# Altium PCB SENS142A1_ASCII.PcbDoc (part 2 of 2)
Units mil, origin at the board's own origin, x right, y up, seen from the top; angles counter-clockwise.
Board outline 2760 x 2518.85 mil, 4 copper layers (Top Layer, Signal Layer 1, Signal Layer 2, Bottom Layer), stack 62.2 mil thick; 50 components, 21 nets, 98 pads, 258 vias.
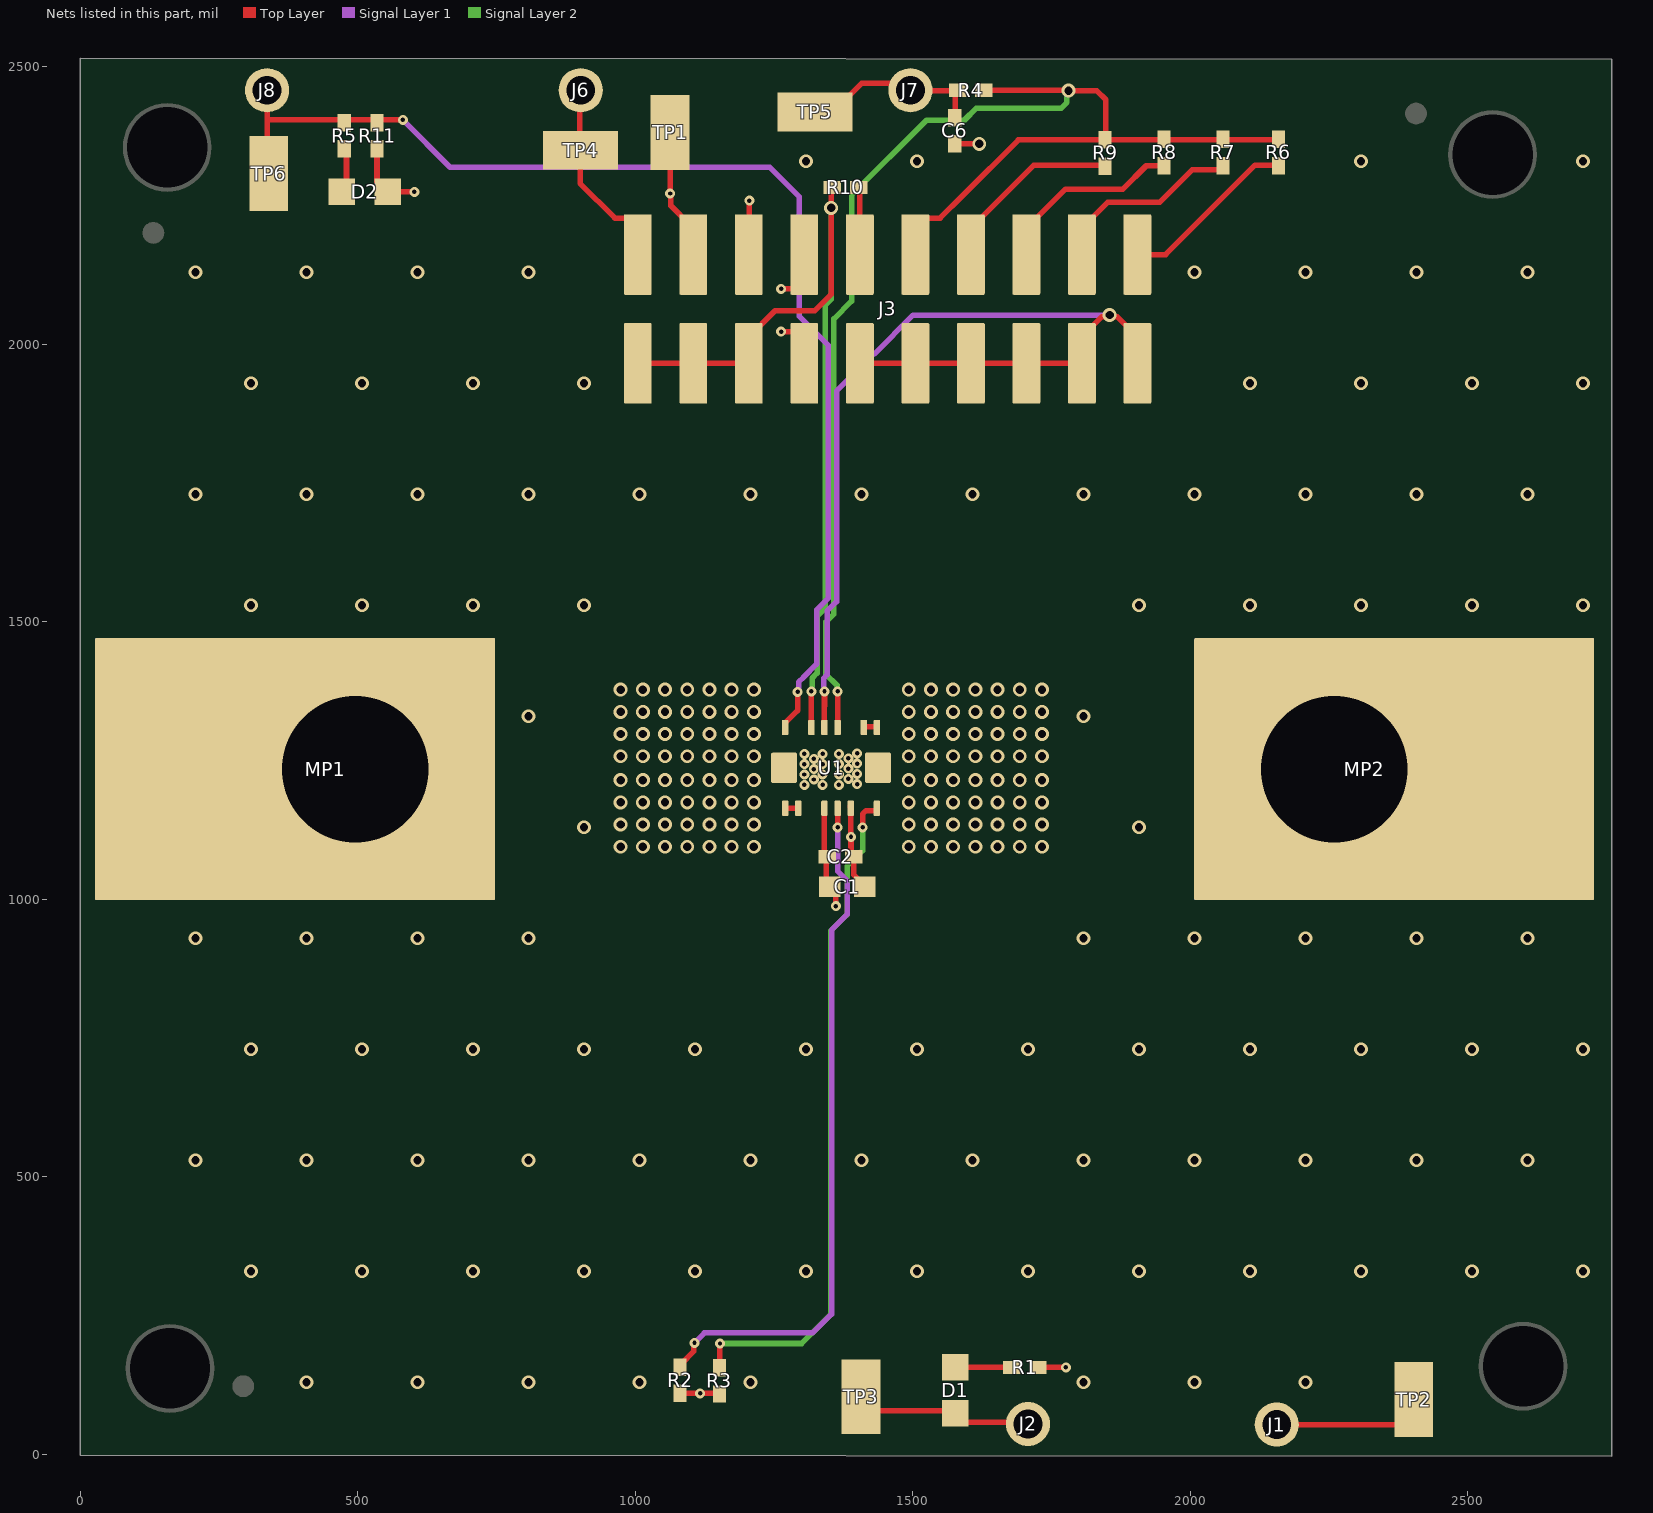
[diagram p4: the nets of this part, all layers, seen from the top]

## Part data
C1: library part CMP-0007029-4, "CAP, CERM, 1 uF, 50 V, +/- 10%, X6S, 0603"
C2: library part CMP-0006675-2, "CAP, CERM, 0.1 uF, 50 V, +/- 20%, X7R, 0402"
C6: library part CMP-0006333-1, "CAP, CERM, 0.01 uF, 100 V, +/- 10%, X7S, AEC-Q200 Grade 1, 0402"
D1 D2: library part CMP-0002885-2, "LED, White, SMD"
FID1 FID2 FID3: library part CMP-0077181-1, "Fiducial mark.  There is nothing to buy or mount."
H1 H2 H3 H4: library part CMP-0003622-1, "Bumpon, Hemisphere, 0.375 X 0.235, Black"
J1 J2 J6 J7 J8: library part CMP-0086763-1, "CONN PIN RCPT .018-.021 SOLDER"
J3: library part CMP-0075600-2, "Header, 2.54mm, 10x2, Gold, SMT"
LBL1: library part CMP-0003625-1, "Thermal Transfer Printable Labels, 0.650\" W x 0.200\" H - 10,000 per roll"
LOGO1: library part CMP-0074835-1, "IEC 61010-1 High Voltage Warning"
Logo2: library part CMP-0074847-1, "FCC_disclaimer"
LOGO3: library part CMP-0074844-1
Logo4: library part CMP-0074837-2, "IEC 61010-1 Hot Surface Warning"
MP1 MP2: library part CMP-0121463-2, "Terminal Connector Rectangular Lug, Grounding 1/4 Stud"
R1 R5 R8 R11: library part CMP-0025958-3, "RES, 10.0 k, 1%, 0.063 W, AEC-Q200 Grade 0, 0402"
R2 R3 R4: library part CMP-0027004-2, "RES, 0, 5%, 0.063 W, 0402"
R6: library part CMP-0026162-1, "RES, 20.0 k, 1%, 0.063 W, 0402"
R7: library part CMP-0026027-2, "RES, 15.0 k, 1%, 0.063 W, 0402"
R9 R10: library part CMP-0026414-1, "RES, 4.99 k, 1%, 0.063 W, 0402"
SH-J1 SH-J2 SH-J3: library part CMP-0003642-1, "Shunt, 100mil, Flash Gold, Black"
TP1 TP2 TP3 TP4 TP5 TP6: library part CMP-0055152-1, "Test Point, Miniature, SMT"
U1: library part CMP-0122809-2, "-4V to 110V, Bidirectional, Ultra-Precise, Current Sense Amplifier with Enhanced PWM Rejection and 35A EZShuntTM Technology"
ZZ1: library part CMP-0003616-3
ZZ2: library part CMP-0077236-1
ZZ3: library part CMP-0077237-1
ZZ4: library part CMP-0077238-1

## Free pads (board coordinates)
  round 160 hole 145: 3(157,2355) 3(162,155) 3(2545,2342.12) 3(2600,159)

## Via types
v1: diameter 25, hole 15, Top Layer to Bottom Layer, tented both sides, 218 vias
v2: diameter 18, hole 8, Top Layer to Bottom Layer, tented both sides, 40 vias

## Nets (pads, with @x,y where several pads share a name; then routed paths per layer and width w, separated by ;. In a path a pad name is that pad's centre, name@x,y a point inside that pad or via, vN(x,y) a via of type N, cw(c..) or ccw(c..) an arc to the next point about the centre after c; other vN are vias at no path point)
ALERT: J8.1 R5.2 R11.2 TP6.1 U1.13 | length 2150.9
  Top Layer w10: TP6.1@337,2322 337,2406 ; J8.1@337,2446 337,2406 ; v2(581.45,2404.5) 338.5,2404.5 337,2406 ; U1.13@1270.32,1309.96 1270.32,1317.83 1293,1340.51 1293,1348 ; v2(1293,1374) 1293.26,1373.74 1293.26,1348
  Signal Layer 1 w10: v2(581.45,2404.5) 666.95,2319 1243,2319 1295.59,2266.41 1295.59,2050.97 1348.19,1998.38 1348.19,1543 1327,1521.81 1327,1424.25 1303.87,1401.13 ; v2(1293,1374) 1294.53,1375.53 1294.53,1391.53 1304,1401
Ext_REF: J3.2 J6.1 TP4.1 | length 301.7
  Top Layer w10: TP4.1@900,2342 J6.1@900,2458 ; TP4.1@902,2342 901,2341 901,2290.32 963.82,2227.5 1006.5,2227.5 J3.2@1008,2226
FB: J3.9 J3.11 J3.13 J3.15 J3.17 J3.19 U1.11 | length 1826
  Top Layer w10: v2@1341,1376 1341.2,1375.8 U1.11@1341.2,1309.97 ; 1341.22,1349.33 v2(1341.22,1375) ; J3.9@1405,1966 J3.11@1505,1966 J3.13@1605,1966 J3.15@1705,1966 1800,1966 J3.17@1804,1962 ; J3.17@1795,1981 1795,2003.5 1841.63,2050.13 1852.13,2050.13 v1(1855,2053) 1857.87,2050.13 1868.37,2050.13 1913,2005.5 J3.19@1913,1951
  Signal Layer 1 w10: v2@1341,1376 1340,1377 1340,1399 1346,1405 1346,1519.59 1363.19,1536.78 1363.19,1916.19 1430.5,1983.5 ; 1431,1983 1501,2053 v1(1855,2053)
GND: C1.2 C2.2 C6.1 J1.1 J3.4 J3.7 J3.8 R1.1 R2.2 R3.2 TP1.1 TP2.1 U1.5 | length 852.5
  Top Layer w10: TP1.1@1065,2388 1063,2386 TP1.1@1063,2382 v2(1063,2272) 1064.53,2270.47 1064.53,2249.97 1100,2214.5 J3.4@1100,2198 ; R2.2@1081,110 v2(1117,110) R3.2@1154,110 ; v2(1263,2023) 1293,2023 J3.7@1294,2022 ; v2(1263,2100) J3.8@1290,2100 ; U1.5@1388,1167 1388.72,1166.28 1388.72,1113.28 v2(1389,1113) 1389,1081.62 C2.2@1393.62,1077 1393.62,1044.7 1407.32,1031 C1.2@1407.5,1031 ; C6.1@1576,2361.38 v1(1620,2361.38) ; R1.1@1726,158 1727,157 v2@1777,157 ; J1.1@2156,54 2373,54 2403,84 TP2.1@2403,99
  Top Layer w20: C1.2@1421,1016.68 C1.2@1421.66,1017.35
  other v2: 1776,157
IN+: U1.1 U1.2 | length 23.8
  Top Layer w10: U1.1@1270.32,1164.29 1293.71,1164.29 U1.2@1294,1164
IN-: U1.8 U1.9 | length 21.5
  Top Layer w10: U1.9@1412.05,1309.96 1412.05,1310.09 1412.96,1311 U1.8@1433,1311
IS+: MP1.1 U1.14
  other v1: 408,130.12 608,130.12 808,130.12 1008,130.12 1208,130.12 308,330.12 508,330.12 708,330.12 908,330.12 1108,330.12 1308,330.12 208,530.12 408,530.12 608,530.12 808,530.12 1008,530.12 1208,530.12 308,730.12 508,730.12 708,730.12 908,730.12 1108,730.12 1308,730.12 208,930.12 408,930.12 608,930.12 808,930.12 974,1095 1014,1095 1054,1095 1094,1095 1134,1095 1174,1095 1214,1095 908,1130.12 974,1135 1014,1135 1054,1135 1094,1135 1134,1135 1174,1135 1214,1135 974,1175 1014,1175 1054,1175 1094,1175 1134,1175 1174,1175 1214,1175 974,1215 1014,1215 1054,1215 1094,1215 1134,1215 1174,1215 1214,1215 974,1258 1014,1258 1054,1258 1094,1258 1134,1258 1174,1258 1214,1258 974,1298 1014,1298 1054,1298 1094,1298 1134,1298 1174,1298 1214,1298 808,1330.12 974,1338 1014,1338 1054,1338 1094,1338 1134,1338 1174,1338 1214,1338 974,1378 1014,1378 1054,1378 1094,1378 1134,1378 1174,1378 1214,1378 308,1530.12 508,1530.12 708,1530.12 908,1530.12 208,1730.12 408,1730.12 608,1730.12 808,1730.12 1008,1730.12 1208,1730.12 308,1930.12 508,1930.12 708,1930.12 908,1930.12 208,2130.12 408,2130.12 608,2130.12 808,2130.12 1308,2330.12
  other v2: 1305.08,1206.64 1338.08,1206.64 1322.08,1216.21 1305.08,1225.21 1338.08,1225.21 1322.08,1234.78 1305.08,1243.78 1338.08,1243.78 1322.08,1253.36 1305.08,1262.36 1338.08,1262.36
IS-: MP2.1 U1.7
  other v1: 1808,130.12 2008,130.12 2208,130.12 1508,330.12 1708,330.12 1908,330.12 2108,330.12 2308,330.12 2508,330.12 2708,330.12 1408,530.12 1608,530.12 1808,530.12 2008,530.12 2208,530.12 2408,530.12 2608,530.12 1508,730.12 1708,730.12 1908,730.12 2108,730.12 2308,730.12 2508,730.12 2708,730.12 1808,930.12 2008,930.12 2208,930.12 2408,930.12 2608,930.12 1493,1095 1533,1095 1573,1095 1613,1095 1653,1095 1693,1095 1733,1095 1908,1130.12 1493,1135 1533,1135 1573,1135 1613,1135 1653,1135 1693,1135 1733,1135 1493,1175 1533,1175 1573,1175 1613,1175 1653,1175 1693,1175 1733,1175 1493,1215 1533,1215 1573,1215 1613,1215 1653,1215 1693,1215 1733,1215 1493,1258 1533,1258 1573,1258 1613,1258 1653,1258 1693,1258 1733,1258 1493,1298 1533,1298 1573,1298 1613,1298 1653,1298 1693,1298 1733,1298 1808,1330.12 1493,1338 1533,1338 1573,1338 1613,1338 1653,1338 1693,1338 1733,1338 1493,1378 1533,1378 1573,1378 1613,1378 1653,1378 1693,1378 1733,1378 1908,1530.12 2108,1530.12 2308,1530.12 2508,1530.12 2708,1530.12 1408,1730.12 1608,1730.12 1808,1730.12 2008,1730.12 2208,1730.12 2408,1730.12 2608,1730.12 2108,1930.12 2308,1930.12 2508,1930.12 2708,1930.12 2008,2130.12 2208,2130.12 2408,2130.12 2608,2130.12 1508,2330.12 2308,2330.12 2708,2330.12
  other v2: 1367,1206.69 1400.08,1207.64 1384.08,1217.21 1367,1225.27 1400.08,1226.21 1384.08,1235.78 1367,1243.84 1400.08,1244.78 1384.08,1254.36 1367,1262.41 1400.08,1263.36
NC4: R2.1 U1.4 | length 1255.8
  Top Layer w10: R2.1@1084,153 1084,164.18 1105.47,185.65 1105.47,199.47 v2(1107,201) ; v2(1365,1130) 1364.91,1130.09 1364.91,1163.91 U1.4@1365,1164
  Signal Layer 1 w10: v2(1107,201) 1125,219 1320,219 1354,253 1354,945 1382,973 1382,1034 1365,1051 v2(1365,1130)
NC6: R3.1 U1.6 | length 1219.7
  Top Layer w10: R3.1@1153,160 1152.5,160.5 1152.5,199.5 v2(1153,200) ; v2(1410,1130) 1410,1154 1416,1160 1434.77,1160 1436,1161.23 U1.6@1436,1165
  Signal Layer 2 w10: v2(1153,200) 1300,200 1353,253 1353,943.97 1382,972.97 1382,1060 1410,1088 v2(1410,1130)
NetD1_2: D1.2 R1.2 | length 96.5
  Top Layer w10: D1.2@1577,157 R1.2@1673.5,157
NetD2_2: D2.2 R5.1 | length 70
  Top Layer w10: D2.2@471.66,2275 480,2283.34 R5.1@480,2341.5
NetJ3_10: J3.10 R10.2 | length 114.9
  Top Layer w10: J3.10@1398,2172 1405,2179 1405,2280.62 R10.2@1402.62,2283
NetJ3_14: J3.14 R9.2 | length 333
  Top Layer w10: J3.14@1605,2162 1605,2209.5 1718.5,2323 R9.2@1843,2323 ; R9.2@1846,2327 R9.2@1846.36,2326.64
NetJ3_16: J3.16 R8.1 | length 286.9
  Top Layer w10: J3.16@1707,2216 1711.5,2216 1775.5,2280 1879,2280 1921,2322 R8.1@1950,2322
NetJ3_18: J3.18 R7.2 | length 348.6
  Top Layer w10: J3.18@1805,2162 1805,2209.5 1851.5,2256 1945,2256 2004,2315 2052.19,2315 2059,2321.81 R7.2@2059,2322.38
NetJ3_20: J3.20 R6.2 | length 321.7
  Top Layer w10: J3.20@1905,2162 1956,2162 2117,2323 R6.2@2160,2323
OUT: J3.12 R4.1 R6.1 R7.1 R8.2 R9.1 U1.10 | length 2534
  Top Layer w10: U1.10@1364.81,1309.96 1364.91,1310.05 1364.91,1374.91 v2(1365,1375) ; J3.12@1505,2162 1505,2207.5 1525,2227.5 1549.5,2227.5 1590,2268 1690.62,2368.62 R9.1@1847,2368.62 ; R4.1@1628.62,2458 v1@1780,2458 ; v1(1781,2457.38) 1831.62,2457.38 1848,2441 R9.1@1848,2372 ; R9.1@1850,2368.62 2163.62,2368.62 R6.1@2164,2369
  Signal Layer 2 w10: 1363.47,1386.01 1344,1405.48 1344,1419 1344,1500 1358,1514 1358,2046 1390,2078 1390,2269 1525,2404 1593,2404 1615,2426 1768,2426 1778.13,2436.13 1778.13,2453.13 v1@1784,2459 ; 1364,1386 1364,1376 v2(1365,1375) v2@1365,1377.16
OUT_FLT: C6.2 J7.1 R4.2 TP5.1 | length 336.5
  Top Layer w10: TP5.1@1324,2419 1356.5,2419 1408.5,2471 1489,2471 J7.1@1503,2457 ; J7.1@1497,2457 J7.1@1503,2457 ; J7.1@1504,2456 J7.1@1503,2457 ; C6.2@1576,2408.62 1577,2409.62 1577,2457 J7.1@1503,2457
REF: J3.1 J3.3 J3.5 R10.1 U1.12 | length 1587.3
  Top Layer w10: J3.1@1005,1966 J3.3@1105,1966 1197,1966 J3.5@1199,1964 ; J3.5@1205,1974 1205,2013.5 1252.5,2061 1324,2061 1353.28,2090.28 v1(1353.28,2246.1) R10.1@1353.28,2282 ; v2@1317,1375 1317.58,1374.42 U1.12@1317.58,1309.97 ; 1317.6,1349.33 v2(1317.6,1375)
  Signal Layer 1 w10: v2@1317.6,1377.16 v2(1317.6,1375) v2@1319.13,1376.53
  Signal Layer 2 w10: v2(1317.6,1375) 1319.13,1376.53 1319.13,1398.91 1328,1407.78 1328,1510 1343,1525 1343,2071 1353.28,2081.28 v1(1353.28,2246.1)
VS: C1.1 C2.1 D1.1 D2.1 J2.1 J3.6 R11.1 TP3.1 U1.3 | length 681.7
  Top Layer w10: R11.1@535,2341.5 535,2294.34 D2.1@554.34,2275 v2(602.49,2275) ; J3.6@1205,2188 1206,2189 v2(1206,2259) ; U1.3@1341.19,1164.29 1341.19,1080.81 C2.1@1345,1077 ; C1.1@1344.5,1031 C2.1@1344.5,1075.58 ; C1.1@1357.5,1021.19 1361.89,1016.8 v2(1361.89,988.19) ; TP3.1@1407,104 1432,79 D1.1@1577,79 ; D1.1@1577,74.32 1593.32,58 1705,58 J2.1@1708,55
pads on no net: FID1.1 FID2.1 FID3.1 H1.0 H2.0 H3.0 H4.0 LBL1.0 SH-J1.0 SH-J2.0 SH-J3.0

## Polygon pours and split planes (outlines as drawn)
IS+ on Bottom Layer "BOTTOM_LAYER_IS+_P032" (solid, remove dead copper, pour order 32): 0,0 1350,0 1350,2517 0,2517
IS- on Bottom Layer "BOTTOM_LAYER_IS-_P034" (solid, remove dead copper, pour order 34): 1350,0 2760,0 2760,2517 1350,2517
IS- on Top Layer "TOP_LAYER_IS-_P028" (solid, remove dead copper, pour order 28): 1350,0 2760,0 2760,2517 1350,2517
IS+ on Top Layer "TOP_LAYER_IS+_P026" (solid, remove dead copper, pour order 26): 1.72,5 1351.72,5 1351.72,2522 1.72,2522
GND on Signal Layer 2 "SIGNAL_LAYER_2_GND_P054" (solid, remove dead copper, pour order 54): 0,0 2760,0 2760,2518 0,2517
GND on Signal Layer 2 "SIGNAL_LAYER_2_GND_P049" (solid, remove dead copper, pour order 49): 2765,-1 2758,6 2758,2514 0,2514 -14,2500 -19,2500 2,2521 12,2511 2760,2511 2760,4 2758,2 2758,-1
VS on Signal Layer 1 "SIGNAL_LAYER_1_VS_P053" (solid, remove dead copper, pour order 53): 0,0 2760,0 2760,2517 0,2517

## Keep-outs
Keep-Out Layer:
  text ".Layer_Name" at 277,-994.37 h60

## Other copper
Top Layer:
  text ".Layer_Name" at 277,-994.37 h60
Bottom Layer:
  text ".Layer_Name" at 277,-994.37 h60

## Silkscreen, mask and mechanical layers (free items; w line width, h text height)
Top Overlay:
  lines w10: 983,1647 1224,1647 ; 1382,1647 1940,1647
  text "OUT" at 1156,2437 h30
  text "Ext" at 825,2249 h30
  text "ALERT" at 330,2155 h30
  text "10 5X" at 1887,1884 h40 r270
  text "9 4X" at 1788,1850 h40 r270
  text "2 GND" at 1086,1849 h40 r270
  text "3 VS" at 1186,1849 h40 r270
  text "6" at 1489,1849 h40 r270
  text "7 2X" at 1586,1849 h40 r270
  text "8 3X" at 1688,1849 h40 r270
  text "4 GND" at 1286,1848 h40 r270
  text "5*" at 1385,1848 h40 r270
  text "1 Ext" at 985,1844 h40 r270
  text "1X" at 1490,1842 h40 r270
  text "REF" at 1050,1590 h40
  text "Gain (*Remove for 1X)" at 1376,1590 h40
  text "IS+" at 452,902 h40
  text "IS-" at 2264,898 h40
  text "DANGER HIGH VOLTAGE" at -282,604 h80
  text "CAUTION HOT SURFACE" at 1367,426 h80
  text "'.PRJ_Title' / .PRJ_Number.SCH_REV" at 63,425.62 h40
  text ".Layer_Name" at 277,-994.37 h60
Bottom Overlay:
  text ".Layer_Name" at 277,-994.37 h60
Top Paste:
  text ".Layer_Name" at 277,-994.37 h60
Bottom Paste:
  text ".Layer_Name" at 277,-994.37 h60
Top Solder:
  text ".Layer_Name" at 277,-994.37 h60
  text ".Layer_Name" at 277,-994.37 h60
Bottom Solder:
  text ".Layer_Name" at 277,-994.37 h60
Drill Guide:
  text ".Layer_Name" at 277,-994.37 h60
M1 Board Outline:
  the board outline again, w10
  text ".Layer_Name" at 277,-994.37 h60
M2 Board Dimensions:
  rectangle: -353,-547.88 -228,-422.88
  rectangle: -228,-671.88 147,-546.88
  text ".Layer_Name" at 277,-994.37 h60
M3 3D STEP Top:
  text ".Layer_Name" at 277,-994.37 h60
M4 3D STEP Bottom:
  text ".Layer_Name" at 277,-994.37 h60
M5 Assembly Top:
  text "COMPONENTS MARKED 'DNP' SHOULD NOT BE POPULATED." at 877,-370.88 h60
  text "ASSEMBLY VARIANT:" at 853,-569.88 h60
  text ".VariantName" at 1889,-569.88 h60
  text "PCB VIEWED FROM TOP SIDE" at -528.5,-791.54 h60
  text "BOARD #:" at 1948,-791.54 h60
  text ".PRJ_Number" at 2493.5,-791.54 h60
  text "REV:" at 3338,-791.54 h60
  text ".PCB_Rev" at 3629.5,-791.54 h60
  text "SVN REV:" at 4176,-791.54 h60
  text ".VersionControl_RevNumber" at 4682,-791.54 h60
  text "TID #:" at 1948,-994.88 h60
  text ".TID" at 2493.5,-994.88 h60
  text "PLOT NAME =" at -528.5,-1200.21 h60
  text ".plot_File_Name" at 277,-1200.21 h60
  text "GENERATED    :" at 1950,-1200.21 h60
  text ".Print_Date" at 2819.5,-1200.21 h60
  text ".Print_Time" at 3548.5,-1200.21 h60
  text "TEXAS INSTRUMENTS" at 4813,-1200.21 h60
M6 Assembly Bottom:
  text "COMPONENTS MARKED 'DNP' SHOULD NOT BE POPULATED." at 5773,24.12 h60
  text ".VariantName" at 4758,-569.88 h60
  text "ASSEMBLY VARIANT:" at 5797,-569.88 h60
  text ".VersionControl_RevNumber" at 735.5,-792.04 h60
  text "SVN REV:" at 1241.5,-792.04 h60
  text ".PCB_Rev" at 1788,-792.04 h60
  text "REV:" at 2079.5,-792.04 h60
  text ".PRJ_Number" at 2924,-792.04 h60
  text "BOARD #:" at 3469.5,-792.04 h60
  text "PCB VIEWED FROM BOTTOM SIDE" at 5946,-792.04 h60
  text ".TID" at 2924,-995.38 h60
  text "TID #:" at 3469.5,-995.38 h60
  text "TEXAS INSTRUMENTS" at 604.5,-1200.71 h60
  text ".Print_Time" at 1869,-1200.71 h60
  text ".Print_Date" at 2598,-1200.71 h60
  text "GENERATED    :" at 3467.5,-1200.71 h60
  text ".plot_File_Name" at 5140.5,-1200.71 h60
  text "PLOT NAME =" at 5946,-1200.71 h60
M9 Title Sheet:
  text "1" at 439.84,7900.62 h70
  text "2" at 2935.5,7900.62 h70
  text "3" at 5424.84,7900.62 h70
  text "4" at 7931.51,7900.62 h70
  text "5" at 10430.5,7900.62 h70
  text "6" at 12935.5,7900.62 h70
  text "A" at -716.5,6757.62 h70
  text "A" at 14083.5,6757.62 h70
  text "B" at -716.5,4377.62 h70
  text "B" at 14083.5,4377.62 h70
  text "C" at -716.5,2002.62 h70
  text "C" at 14083.5,2002.62 h70
  text "PROJECT TITLE:" at 11043.5,141.62 h45
  text ".PRJ_Title" at 11093.5,8.3 h70
  text "DESIGNED FOR:" at 11043.5,-159.38 h45
  text ".PRJ_Customer" at 11093.5,-299.38 h70
  text "D" at -716.5,-367.38 h70
  text "D" at 14083.5,-367.38 h70
  text "FILE NAME:" at 11043.5,-459.38 h45
  text ".PCB_File_Name_No_Path" at 11093.5,-579.38 h70
  text "Texas Instruments (TI) and/or its licensors do not warrant the accuracy or completeness of this specification" at 6074,-741.22 h45
  text "ENGINEER:" at 11043.5,-749.38 h45
  text "LAYOUT BY:" at 12548.5,-749.38 h45
  text "or any information contained therein. TI and/or its licensors do not warrant that this design will meet" at 6029.01,-853.88 h45
  text ".PRJ_Engineer" at 11093.5,-904.37 h70
  text ".PCB_Layout" at 12599,-904.37 h70
  text "the specifications, will be suitable for your application or fit for any particular purpose, or will operate in" at 6029.01,-966.55 h45
  text ".Layer_Name" at 277,-994.37 h60
  text "ALTIUM DESIGNER VERSION:" at 12548.5,-1059.38 h45
  text "an implementation. TI and/or its licensors do not warrant that the design is production worthy. You should" at 6029.01,-1079.21 h45
  text "completely validate and test your design implementation to confirm the system functionality for your application." at 6074,-1191.88 h45
  text ".print_Scale" at 11093.5,-1192.7 h70
  text ".Application_BuildNumber" at 12599,-1192.7 h70
  text "1" at 439.84,-1399.38 h70
  text "2" at 2935.5,-1399.38 h70
  text "3" at 5424.84,-1399.38 h70
  text "4" at 7931.51,-1399.38 h70
  text "5" at 10430.5,-1399.38 h70
  text "6" at 12935.5,-1399.38 h70
M10 Fab Notes:
  text "DESIGN INFORMATION" at 12082.02,6220.3 h60
  text "MIN. TRACK WIDTH:" at 11437.46,6088.17 h60
  text "8" at 12533.7,6088.17 h60
  text "MIL" at 12688.46,6088.17 h60
  text "mm" at 12812,5968.12 h60
  text "MIN. CLEARANCE:" at 11437.46,5964.04 h60
  text "0.127" at 12473.7,5964.05 h60
  text "MIN. VIA PAD SIZE:" at 11437.46,5839.92 h60
  text "18" at 12503.71,5839.92 h60
  text "MIL" at 12688.46,5839.92 h60
  text "5 MIL" at 12132.46,5710.02 h60
  text "MINIMUM ANNULAR RING" at 11108.23,5701.8 h60
  text "EXTERNAL" at 12840.46,5701.8 h60
  text "PER" at 11308.23,5591.67 h60
  text "IPC-D-275 CLASS 2 LEVEL C" at 11528.23,5591.67 h60
  text "MIL, HOLES" at 13016.46,5491.19 h60
  text "+/-" at 12624,5482.61 h60
  text "+/-" at 13478,5482.61 h60
  text "REGISTRATION TOLERANCES:" at 11108.23,5481.54 h60
  text "METAL" at 12308,5481.54 h60
  text "5" at 12884.2,5481.54 h60
  text "3" at 13717.2,5481.54 h60
  text "MIL" at 13833.46,5481.54 h60
  text "HOLE SIZE TOLERANCE (UNLESS OTHERWISE SPECIFIED):" at 11108.23,5383.23 h60
  text "+/-" at 13478,5380.35 h60
  text "3" at 13717.2,5379.29 h60
  text "MIL" at 13833.46,5379.29 h60
  text "MATERIAL:" at 11033.46,5241.64 h60
  text "FR-4 High Tg" at 12019.9,5113.12 h60
  text "X" at 11875.46,5105.13 h60
  text "FR-408" at 11454.46,5100.61 h60
  text "OTHER" at 12942.46,5100.61 h60
  text "63 MIL (1.6mm) +/-10%" at 11774.56,4957.58 h60
  text "X" at 11654.46,4955.13 h60
  text "THICKNESS:" at 11108.23,4949.36 h60
  text "OTHER" at 13059.46,4949.36 h60
  text "TOLERANCE:" at 11108.23,4811.05 h60
  text "X" at 11956.46,4811.05 h60
  text "ANSI IPC-6012 TYPE 3 CLASS 2" at 12134.48,4811.05 h60
  text "OTHER +/-" at 12134.46,4666.86 h60
  text "BOW & TWIST:" at 11108.23,4521.67 h60
  text "X" at 11956.46,4521.67 h60
  text "ANSI IPC-6012 TYPE 3 CLASS 2" at 12134.48,4521.67 h60
  text "OTHER +/-" at 12134.46,4374.97 h60
  text "DRILLING:" at 11033.46,4244.35 h60
  text "NC_DRILL FILES" at 12794.46,4139.16 h60
  text "REFERENCE:" at 11108.23,4135.23 h60
  text "X" at 11765.46,4135.13 h60
  text "AS SHOWN" at 11943.46,4135.23 h60
  text "X" at 12666.46,4135.23 h60
  text "OTHER" at 13092.46,3992.97 h60
  text "PTH COPPER THICKNESS:" at 11107.91,3989.45 h60
  text "X" at 12247.14,3989.45 h60
  text "20-30 um" at 12375.14,3989.45 h60
  text "BOARD FINISH:" at 11033.46,3841.85 h60
  text "SILKSCREEN:" at 11188.68,3731.72 h60
  text "X" at 12146.46,3731.72 h60
  text "TOP" at 12263.46,3731.72 h60
  text "X" at 12656.46,3731.72 h60
  text "BOTTOM" at 12774.46,3731.72 h60
  text "SILKSCREEN COLOR:" at 11188.68,3576.53 h60
  text "X" at 12145.46,3576.53 h60
  text "WHITE" at 12263.46,3576.53 h60
  text "OTHER" at 12774.46,3576.53 h60
  text "X" at 12276.46,3433.09 h60
  text "GREEN" at 12394.46,3433.09 h60
  text "OTHER" at 13012.46,3433.09 h60
  text "SOLDER RESIST COLOR:" at 11188.68,3426.22 h60
  text "X" at 12276.46,3278.83 h60
  text "MATTE" at 12394.46,3278.83 h60
  text "SEMI-GLOSS" at 13012,3278.2 h60
  text "IMMERSION GOLD (ENIG)" at 12094.46,3106.06 h60
  text "ENEPIG" at 13432,3098.84 h60
  text "SURFACE FINISH:" at 11033.46,3097.84 h60
  text "X" at 11916.46,3097.84 h60
  text "IMM. TIN/SILVER OR EQUIV" at 11363,2960.53 h60
  text "OTHER" at 12794.46,2956.59 h60
  text "ARRAY/PANEL:" at 11033.46,2801.21 h60
  text "CUT AND TRIM PER M1 BOARD OUTLINE" at 12094.46,2792.99 h60
  text "N.C. ROUTE" at 12094.46,2657.02 h60
  text "X" at 12782.46,2657.02 h60
  text "V. SCORE" at 12960.46,2657.02 h60
  text "CERTIFICATION:" at 11033.46,2527.9 h60
  text "MATERIALS AND WORKMANSHIP FOR ALL PCBS" at 11758.46,2527.9 h60
  text "TO MEET OR EXCEED THE REQUIREMENTS OF:" at 11758.46,2433.83 h60
  text "X" at 11395.97,2305.2 h60
  text "ANSI IPC-A-600F CLASS ->" at 11523.96,2305.2 h60
  text "X" at 13171.97,2305.2 h60
  text "2" at 13281.96,2305.2 h60
  text "1" at 12966.96,2303.71 h60
  text "3" at 13635.96,2303.71 h60
  text "X" at 12207.97,2157.52 h60
  text "RoHS" at 12335.96,2157.52 h60
  text "OTHER" at 12980.36,2157.52 h60
  text "PER ORDER" at 13377.42,2157.52 h60
  text "ALL BOARDS MUST MEET OR EXCEED UL94-V0 REQUIREMENTS." at 11061,2003.69 h60
  text "PCB MUST BEAR THE UL94V-0 UL REGISTERED MATERIAL ID NUMBER" at 11061,1887.63 h60
  text "ADDITIONAL REQUIREMENTS:" at 11033.46,1718.2 h60
  text "MICROSECTION:" at 11108.23,1611.08 h60
  text "NO" at 12013.96,1611.08 h60
  text "X" at 12321,1479.12 h60
  text "REQUIRED" at 12875.46,1466.74 h60
  text "BARE BOARD ELEC. TEST:" at 11108.23,1463.89 h60
  text "NONE" at 12413.96,1463.89 h60
  text "PER ORDER" at 13467.46,1463.89 h60
  text "No VIAS REQUIRE NON-CONDUCTIVE FILL AND PLANARIZE" at 11276.38,1258.94 h59
  text "No VIAS REQUIRE CONDUCTIVE FILL AND PLANARIZE" at 11284.38,1154.97 h60
  text "OUTER XX MIL TRACES REQUIRE 50 OHM SINGLE-ENDED IMPEDANCE" at 11283.39,991.58 h58
  text "LAYER 2 & 3 (INNER LAYERS) 17 MIL WIDE, XX MIL SPACE / TRACES REQUIRE 100 OHM DIFFERENTIAL IMPEDANCE" at 11237,649.12 h60 r0.3
  text ".Layer_Name" at 277,-994.37 h60
M11 Gerber Information:
  text "ALL ARTWORK VIEWED FROM TOP SIDE" at -528.5,-791.54 h60
  text "BOARD #:" at 1948,-791.54 h60
  text ".PRJ_Number" at 2493.5,-791.54 h60
  text "REV:" at 3338,-791.54 h60
  text ".PCB_Rev" at 3629.5,-791.54 h60
  text "SVN REV:" at 4176,-791.54 h60
  text ".VersionControl_RevNumber" at 4682,-791.54 h60
  text "LAYER NAME =" at -528.5,-994.37 h60
  text "TID #:" at 1948,-994.88 h60
  text ".TID" at 2493.5,-994.88 h60
  text "PLOT NAME =" at -528.5,-1200.21 h60
  text ".plot_File_Name" at 277,-1200.21 h60
  text "GENERATED    :" at 1950,-1200.21 h60
  text ".Print_Date" at 2819.5,-1200.21 h60
  text ".Print_Time" at 3548.5,-1200.21 h60
  text "TEXAS INSTRUMENTS" at 4813,-1200.21 h60
M12 Stackup:
  drawing of 444 lines, arcs and shapes, not listed
  text "Layer" at 6413.09,5230.71 h60
  text "Name" at 6823,5230.71 h60
  text "Material" at 7762.74,5230.71 h60
  text "Thickness" at 8622.51,5230.71 h60
  text "Constant" at 9272.34,5230.71 h60
  text "Board Layer Stack" at 9842.2,5230.71 h60
  text "Top Overlay" at 6823,5110.71 h60
  text "Top Solder" at 6823,4990.71 h60
  text "Solder Resist" at 7762.74,4990.71 h60
  text "0.40mil" at 8622.51,4990.71 h60
  text "3.5" at 9272.34,4990.71 h60
  text "1" at 6413.09,4870.71 h60
  text "Top Layer" at 6823,4870.71 h60
  text "2.80mil" at 8622.51,4870.71 h60
  text "Dielectric1" at 6823,4750.71 h60
  text "FR-4" at 7762.74,4750.71 h60
  text "17.00mil" at 8622.51,4750.71 h60
  text "4.2" at 9272.34,4750.71 h60
  text "2" at 6413.09,4630.71 h60
  text "Signal Layer 1" at 6823,4630.71 h60
  text "2.80mil" at 8622.51,4630.71 h60
  text "Dielectric 2" at 6823,4510.71 h60
  text "FR-4" at 7762.74,4510.71 h60
  text "17.00mil" at 8622.51,4510.71 h60
  text "4.2" at 9272.34,4510.71 h60
  text "3" at 6413.09,4390.71 h60
  text "Signal Layer 2" at 6823,4390.71 h60
  text "2.80mil" at 8622.51,4390.71 h60
  text "Dielectric 3" at 6823,4270.71 h60
  text "FR-4" at 7762.74,4270.71 h60
  text "17.00mil" at 8622.51,4270.71 h60
  text "4.2" at 9272.34,4270.71 h60
  text "4" at 6413.09,4150.71 h60
  text "Bottom Layer" at 6823,4150.71 h60
  text "2.80mil" at 8622.51,4150.71 h60
  text "Bottom Solder" at 6823,4030.71 h60
  text "Solder Resist" at 7762.74,4030.71 h60
  text "0.40mil" at 8622.51,4030.71 h60
  text "3.5" at 9272.34,4030.71 h60
  text "Bottom Overlay" at 6823,3910.71 h60
  text ".Layer_Name" at 277,-994.37 h60
M13 Component Bodies Top:
  text ".Layer_Name" at 277,-994.37 h60
M14 Component Bodies Bottom:
  text ".Layer_Name" at 277,-994.37 h60
M15 Courtyards Top:
  text ".Layer_Name" at 277,-994.37 h60
M16 Courtyards Bottom:
  text ".Layer_Name" at 277,-994.37 h60
Drill Drawing:
  lines w10: 3034.09,3237.74 3061.72,3251.55 3089.34,3237.74 3075.53,3265.37 3089.34,3292.99 3061.72,3279.18 3034.09,3292.99 3047.9,3265.37 3034.09,3237.74 ; 3034.09,3375.87 3047.9,3375.87 3047.9,3362.06 3075.53,3362.06 3075.53,3375.87 3089.34,3375.87 3089.34,3403.5 3075.53,3403.5 3075.53,3417.31 3047.9,3417.31 3047.9,3403.5 3034.09,3403.5 3034.09,3375.87 ; 3034.09,3486.38 3089.34,3486.38 3089.34,3541.63 3034.09,3541.63 3034.09,3486.38 ; 3034.09,3665.95 3089.34,3665.95 3061.72,3610.7 3034.09,3665.95 ; 3034.09,3735.02 3034.09,3748.83 3047.9,3762.65 3034.09,3776.46 3034.09,3790.27 3047.9,3790.27 3061.72,3776.46 3075.53,3790.27 3089.34,3790.27 3089.34,3776.46 3075.53,3762.65 3089.34,3748.83 3089.34,3735.02 3075.53,3735.02 3061.72,3748.83 3047.9,3735.02 3034.09,3735.02
  lines w12: 2984,3200.44 6142.03,3200.44 ; 2984,3822.04 6142.03,3822.04 ; 3321.86,3076.12 3321.86,3946.36 ; 3624.17,3076.12 3624.17,3946.36 ; 4216.97,3076.12 4216.97,3946.36 ; 4476.11,3076.12 4476.11,3946.36 ; 4851.26,3076.12 4851.26,3946.36 ; 5575.59,3076.12 5575.59,3946.36 ; 2984,3076.12 6142.03,3076.12 6142.03,3946.36 2984,3946.36 2984,3076.12
  text "Symbol" at 3058.59,3859.34 h72
  text "Count" at 3359.16,3859.34 h72
  text "Hole Size" at 3661.47,3859.34 h72
  text "Plated" at 4254.26,3859.34 h72
  text "Hole Type" at 4513.4,3859.34 h72
  text "Drill Layer Pair" at 4888.56,3859.34 h72
  text "Hole Tolerance" at 5612.89,3859.34 h72
  text "40" at 3359.16,3735.02 h60
  text "8.00mil (0.203mm)" at 3661.47,3735.02 h60
  text "PTH" at 4254.26,3735.02 h60
  text "Round" at 4513.4,3735.02 h60
  text "Top Layer - Bottom Layer" at 4888.56,3735.02 h60
  text "218" at 3359.16,3610.7 h60
  text "15.00mil (0.381mm)" at 3661.47,3610.7 h60
  text "PTH" at 4254.26,3610.7 h60
  text "Round" at 4513.4,3610.7 h60
  text "Top Layer - Bottom Layer" at 4888.56,3610.7 h60
  text "5" at 3359.16,3486.38 h60
  text "51.97mil (1.320mm)" at 3661.47,3486.38 h60
  text "PTH" at 4254.26,3486.38 h60
  text "Round" at 4513.4,3486.38 h60
  text "Top Layer - Bottom Layer" at 4888.56,3486.38 h60
  text "4" at 3359.16,3362.06 h60
  text "145.00mil (3.683mm)" at 3661.47,3362.06 h60
  text "PTH" at 4254.26,3362.06 h60
  text "Round" at 4513.4,3362.06 h60
  text "Top Layer - Bottom Layer" at 4888.56,3362.06 h60
  text "2" at 3359.16,3237.74 h60
  text "263.78mil (6.700mm)" at 3661.47,3237.74 h60
  text "NPTH" at 4254.26,3237.74 h60
  text "Round" at 4513.4,3237.74 h60
  text "Top Layer - Bottom Layer" at 4888.56,3237.74 h60
  text "269 Total" at 3359.16,3113.42 h60
  text ".Layer_Name" at 277,-994.37 h60
M17 Embedded Cavity:
  text ".Layer_Name" at 277,-994.37 h60
M18 Embedded Assembly:
  text ".Layer_Name" at 277,-994.37 h60
M19 Embedded Keepout:
  text ".Layer_Name" at 277,-994.37 h60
